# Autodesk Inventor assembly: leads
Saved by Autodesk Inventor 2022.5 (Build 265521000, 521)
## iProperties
Created: 2024-12
Part Number: leads
Document SubType Name: Assembly
Designer: AdminForWorker
Title: leads
Author: AdminForWorker
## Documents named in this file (3)
- c:\worker\convert-fusion-r05-cosv3\tmp\job-1\35\temp\files\545dca92-a972-481a-9197-dd1a1176500e\leads_2.iam
- c:\worker\convert-fusion-r05-cosv3\tmp\job-1\35\temp\files\545dca92-a972-481a-9197-dd1a1176500e\top_lead.ipt
- c:\worker\convert-fusion-r05-cosv3\tmp\job-1\35\temp\files\545dca92-a972-481a-9197-dd1a1176500e\bottom_lead.ipt
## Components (8 placed, 2 different names)
1. top_lead:1
2. top_lead:5
3. top_lead:6
4. top_lead:7
5. bottom_lead:1
6. bottom_lead:8
7. bottom_lead:9
8. bottom_lead:10
